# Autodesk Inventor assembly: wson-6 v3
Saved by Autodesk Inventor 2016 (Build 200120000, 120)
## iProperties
Created: 2016-09
Part Number: wson-6 v3
Document SubType Name: Assembly
Designer: Administrator
Author: Administrator
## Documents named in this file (3)
- c:\worker\convert-fusion-aug-2016\tmp\job-1\13\output\files\2055b865-881d-4af8-ae30-e7b46ec3c804\wson-6 v3.iam
- c:\worker\convert-fusion-aug-2016\tmp\job-1\13\output\files\2055b865-881d-4af8-ae30-e7b46ec3c804\Component28.ipt
- c:\worker\convert-fusion-aug-2016\tmp\job-1\13\output\files\2055b865-881d-4af8-ae30-e7b46ec3c804\lead (2).ipt
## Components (2 placed, 2 different names)
1. Component28:1
2. lead (2):1
